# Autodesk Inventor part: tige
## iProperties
Shininess: 20.0
Angle Display Precision: 2
Document Length Units: 11269
Document Angle Units: 11279
Document Time Units: 11290
Document Mass Units: 11283
Document Length Units Precision: 3
Document Angle Units Precision: 2
Compacted: True
Created: 2002-09
Part Number: tige
Material: Par défaut
Document SubType Name: Modélisation
Designer: administrateur
Density: 0.0
Volumn: 0.0
Area: 0.0
PropertySet Name: Model Information
Control State: 0
Master: False
Checked Out: False
Author: administrateur
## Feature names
1. Extrusion1
2. Extrusion3
